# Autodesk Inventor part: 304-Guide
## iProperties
Author: Philippe
Created: 2001-12
Part Number: 304-Guide
Material: Par défaut
Document SubType Name: Modélisation
Designer: Philippe
Control State: 0
Master: False
Checked Out: False
PropertySet Name: Design Tracking Control
Shininess: 60.0
Angle Display Precision: 2
Document Length Units: 11269
Document Angle Units: 11283
Document Time Units: 11279
Document Mass Units: 11290
Document Length Units Precision: 3
Document Angle Units Precision: 2
Compacted: False
PropertySet Name: _Private Model Information
Density: 0.0
Volumn: 0.0
Area: 0.0
PropertySet Name: Model Information
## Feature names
1. Extrusion1
